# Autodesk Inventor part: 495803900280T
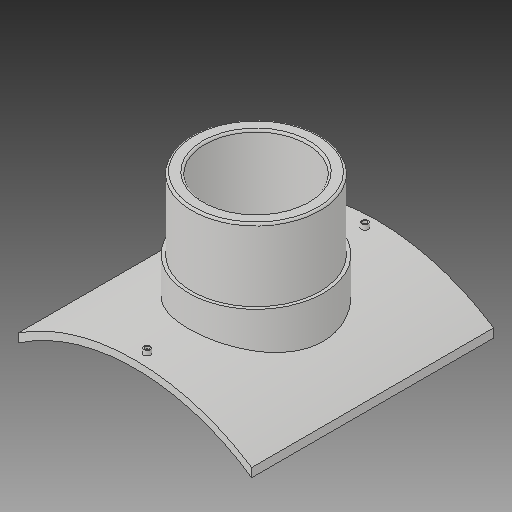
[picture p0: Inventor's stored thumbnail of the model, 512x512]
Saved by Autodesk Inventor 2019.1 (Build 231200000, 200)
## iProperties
Created: 2017-10
Part Number: 495803900280T
Material: Generic
Description: PLASSON BRANCH SADDLE  900x280
Document SubType Name: Modeling
Designer: KIM
Mass: 2754.05 g
Surface Area: 3037.44 cm^2
Volume: 2754.05 cm^3
Density: 1 g/cm^3
Appearance: Default
Author: KIM
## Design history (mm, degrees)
derived "495803.ipt"
feature "Solid1::495803.ipt"
tag "TaggingFeature1"
body "Solid1"
other parameters: "d1" = 16, "d2" = 511, "d4" = 0, "d12" = 475.6, "d13" = 14, "d14" = 238.5, "d16" = 5 deg, "d18" = 4, "d19" = 14, "d20" = 0, "d21" = 3, "d22" = 0, "d23" = 691, "d24" = 294, "d25" = 16, "d26" = 224, "d28" = 0, "d29" = 9.6, "d31" = 0, "d32" = 112.5, "d33" = 0, "d34" = 9, "d37" = 157.5, "d38" = 0, "d39" = 4.5, "B_" = 511, "H_" = 225, "x_" = 16, "D_" = 16
